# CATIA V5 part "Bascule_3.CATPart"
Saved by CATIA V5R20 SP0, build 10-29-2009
Part number: Bascule_3
Publications: "Corps_bascule_3", "Axe_pivot_bascule_3_point_B", "Axe_pivot_bascule_3_point_C", "Plan_ref"
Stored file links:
  C:\Users\J\IAO_2012_jgossard\Bascule_3.CATPart
  C:\Users\J\IAO_2012_jgossard\squelette_mecanisme_presse.CATProduct

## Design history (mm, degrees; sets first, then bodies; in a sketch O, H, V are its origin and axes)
Set1
  Point1 "Point_B": linked copy from another document
  Point2 "Point_C": linked copy from another document
  Plane1 "Plan_ref": linked copy from another document
Body1 (main body)
  Line1 "Corps_bascule_3": type PtPt, FirstPoint Point1, SecondPoint Point2
  Line2 "Axe_pivot_bascule_3_point_B": type Normal, RefPoint Point1, RefSkin Plane1, Start 0, End 10
  Line3 "Axe_pivot_bascule_3_point_C": type Normal, RefPoint Point2, RefSkin Plane1, Start 0, End 10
